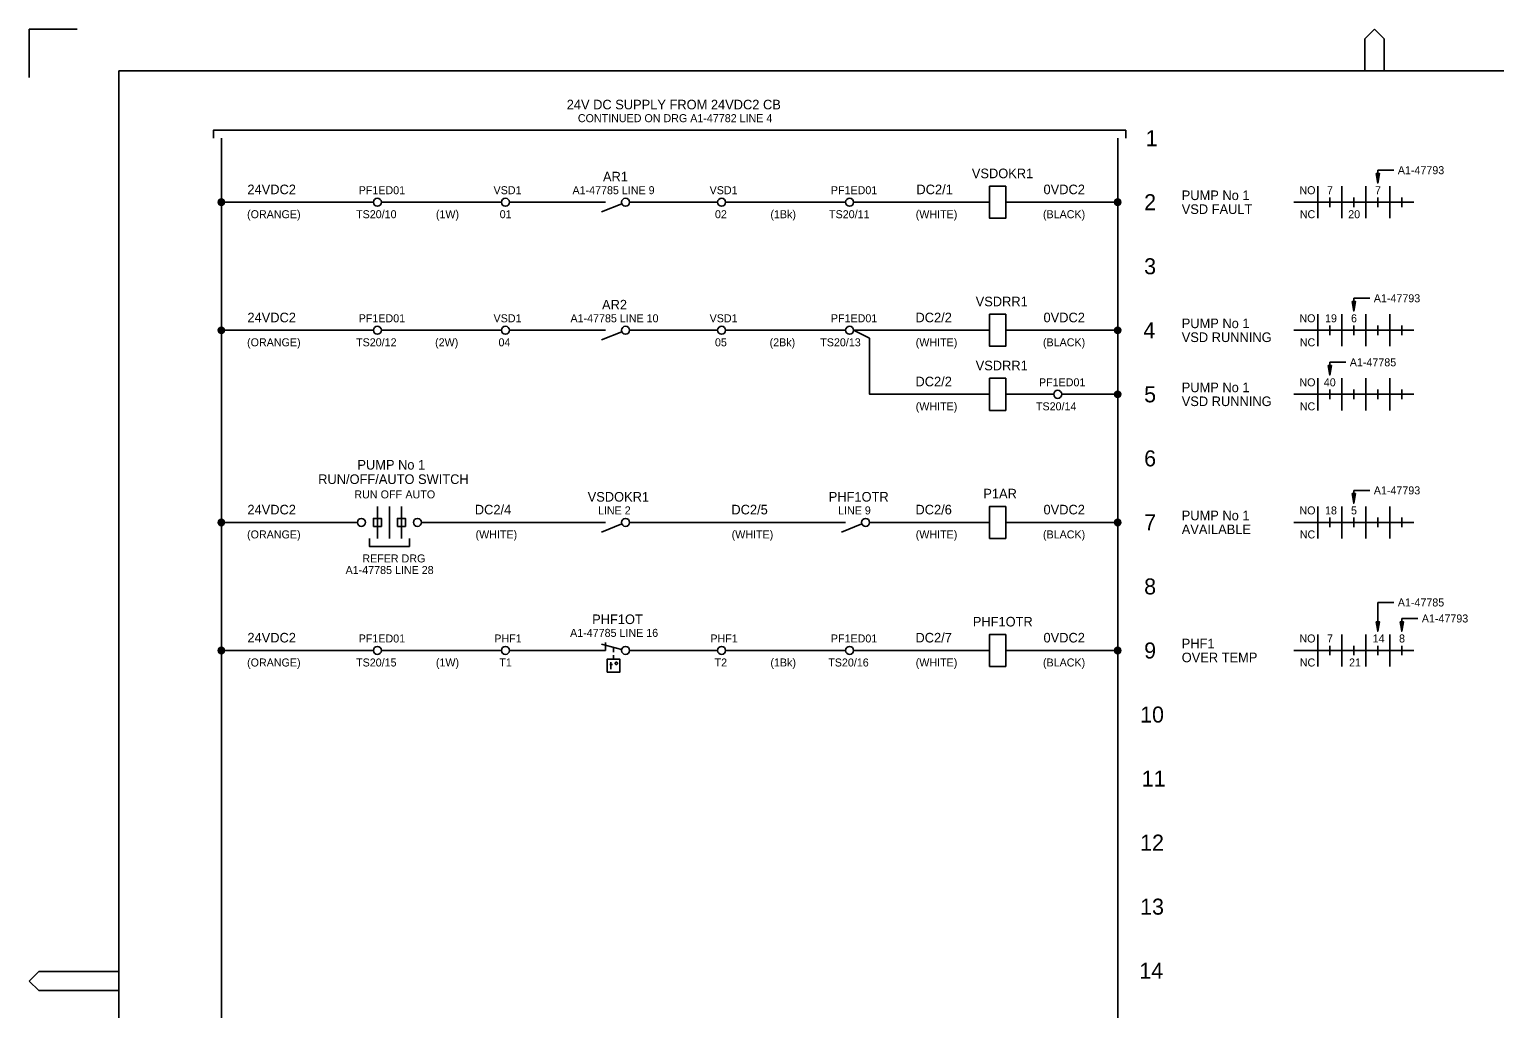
# Model space of a CAD drawing. Extents: x 0 to 841, y 0 to 594.
# Drawn here: x 0 to 457.8, y 288.1 to 594 of the extents above; entities that cross this region are included whole.
import ezdxf

# ---------------------------------------------------------------- set-up
doc = ezdxf.new("R2010")
doc.units = 0
for name, color, linetype in [('A1BORDER', 7, 'Continuous'), ('Level 1', 7, 'Continuous'), ('Level 10', 7, 'Continuous'), ('Level 5', 7, 'Continuous'), ('Level 6', 7, 'Continuous')]:
    doc.layers.add(name, color=color, linetype=linetype)

msp = doc.modelspace()

# ---------------------------------------------------------------- linework, layer by layer
at = {"layer": 'A1BORDER'}
for p, q in [((0, 594), (15, 594)), ((0, 579), (0, 594)), ((417.19, 591), (420.19, 594)), ((417.19, 581), (417.19, 591)), ((423.19, 591), (420.19, 594)), ((423.19, 581), (423.19, 591)), ((28, 581), (829, 581)), ((28, 581), (28, 15)), ((3, 299.76), (0, 296.76)), ((28, 299.76), (3, 299.76)), ((3, 293.76), (0, 296.76)), ((28, 293.76), (3, 293.76))]:
    msp.add_line(p, q, dxfattribs=at)
at = {"layer": 'Level 1'}
for p, q in [((60, 160), (60, 560)), ((340, 160), (340, 560)), ((402.5, 535), (402.5, 545)), ((410, 535), (410, 545)), ((417.5, 535), (417.5, 545)), ((425, 535), (425, 545)), ((406.25, 541.5), (406.25, 538.5)), ((413.75, 541.5), (413.75, 538.5)), ((421.25, 541.5), (421.25, 538.5)), ((428.75, 541.5), (428.75, 538.5)), ((60, 540), (107.5, 540)), ((147.5, 540), (110, 540)), ((177.5, 540), (150, 540)), ((180, 540), (177.5, 540)), ((177.5, 540), (177.5, 540)), ((215, 540), (187.5, 540)), ((187.5, 540), (187.5, 540)), ((255, 540), (217.5, 540)), ((305, 540), (340, 540)), ((395, 540), (432.5, 540)), ((60, 140), (60, 520)), ((340, 140), (340, 520)), ((402.5, 495), (402.5, 505)), ((410, 495), (410, 505)), ((417.5, 495), (417.5, 505)), ((425, 495), (425, 505)), ((60, 500), (107.5, 500)), ((147.5, 500), (110, 500)), ((177.5, 500), (150, 500)), ((180, 500), (177.5, 500)), ((177.5, 500), (177.5, 500)), ((215, 500), (187.5, 500)), ((187.5, 500), (187.5, 500)), ((255, 500), (217.5, 500)), ((305, 500), (340, 500)), ((395, 500), (432.5, 500)), ((406.25, 501.5), (406.25, 498.5)), ((413.75, 501.5), (413.75, 498.5)), ((421.25, 501.5), (421.25, 498.5)), ((428.75, 501.5), (428.75, 498.5)), ((402.5, 475), (402.5, 485)), ((406.25, 481.5), (406.25, 478.5)), ((410, 475), (410, 485)), ((413.75, 481.5), (413.75, 478.5)), ((417.5, 475), (417.5, 485)), ((421.25, 481.5), (421.25, 478.5)), ((425, 475), (425, 485)), ((428.75, 481.5), (428.75, 478.5)), ((305, 480), (320, 480)), ((322.5, 480), (340, 480)), ((395, 480), (432.5, 480)), ((108.75, 445), (108.75, 435)), ((112.5, 445), (112.5, 435)), ((116.25, 445), (116.25, 435)), ((402.5, 435), (402.5, 445)), ((410, 435), (410, 445)), ((417.5, 435), (417.5, 445)), ((425, 435), (425, 445)), ((102.5, 440), (60, 440)), ((177.5, 440), (122.5, 440)), ((180, 440), (177.5, 440)), ((177.5, 440), (177.5, 440)), ((252.5, 440), (187.5, 440)), ((187.5, 440), (187.5, 440)), ((255, 440), (252.5, 440)), ((252.5, 440), (252.5, 440)), ((262.5, 440), (262.5, 440)), ((305, 440), (340, 440)), ((395, 440), (432.5, 440)), ((406.25, 441.5), (406.25, 438.5)), ((413.75, 441.5), (413.75, 438.5)), ((421.25, 441.5), (421.25, 438.5)), ((428.75, 441.5), (428.75, 438.5)), ((402.5, 395), (402.5, 405)), ((410, 395), (410, 405)), ((417.5, 395), (417.5, 405)), ((425, 395), (425, 405)), ((60, 400), (107.5, 400)), ((147.5, 400), (110, 400)), ((177.5, 400), (150, 400)), ((180, 400), (177.5, 400)), ((177.5, 400), (177.5, 400)), ((182.5, 401), (182.5, 399.5)), ((182.5, 398.5), (182.5, 397.25)), ((215, 400), (187.5, 400)), ((187.5, 400), (187.5, 400)), ((255, 400), (217.5, 400)), ((305, 400), (340, 400)), ((395, 400), (432.5, 400)), ((406.25, 401.5), (406.25, 398.5)), ((413.75, 401.5), (413.75, 398.5)), ((421.25, 401.5), (421.25, 398.5)), ((428.75, 401.5), (428.75, 398.5))]:
    msp.add_line(p, q, dxfattribs=at)
for points in [[(57.5, 560), (57.5, 562.5), (342.5, 562.5), (342.5, 560)], [(257.5, 500), (262.5, 497.5), (262.5, 480), (300, 480)], [(106.25, 435), (106.25, 432.5), (118.75, 432.5), (118.75, 435)], [(181.38, 395.63), (182.13, 395.63)], [(181.63, 396.38), (181.63, 394.12)], [(183.36, 395.63), (183.18, 395.67), (183.05, 395.81), (182.99, 396.01), (183.05, 396.19), (183.18, 396.32), (183.36, 396.38), (183.56, 396.32), (183.7, 396.19), (183.74, 396.01), (183.7, 395.81), (183.56, 395.67), (183.36, 395.63)]]:
    msp.add_lwpolyline(points, dxfattribs=at)
for points in [[(107.5, 438.75), (110, 438.75), (110, 441.25), (107.5, 441.25)], [(115, 438.75), (117.5, 438.75), (117.5, 441.25), (115, 441.25)], [(180.5, 393.25), (184.5, 393.25), (184.5, 397.25), (180.5, 397.25)]]:
    msp.add_lwpolyline(points, close=True, dxfattribs=at)
at = {"layer": 'Level 10'}
for p, q in [((59.1, 540.44), (59.1, 539.56)), ((59.4, 540.8), (59.4, 539.2)), ((59.7, 540.95), (59.7, 539.05)), ((60, 541), (60, 539.01)), ((60.3, 540.95), (60.3, 539.05)), ((60.6, 540.8), (60.6, 539.2)), ((60.9, 540.44), (60.9, 539.56)), ((339.1, 540.44), (339.1, 539.56)), ((339.4, 540.8), (339.4, 539.2)), ((339.7, 540.95), (339.7, 539.05)), ((340, 541), (340, 539.01)), ((340.3, 540.95), (340.3, 539.05)), ((340.6, 540.8), (340.6, 539.2)), ((340.9, 540.44), (340.9, 539.56)), ((61, 540), (61, 540)), ((185.09, 539.54), (178.75, 537)), ((341, 540), (341, 540)), ((59.1, 500.44), (59.1, 499.56)), ((59.4, 500.8), (59.4, 499.2)), ((59.7, 500.95), (59.7, 499.05)), ((60, 501), (60, 499.01)), ((60.3, 500.95), (60.3, 499.05)), ((60.6, 500.8), (60.6, 499.2)), ((60.9, 500.44), (60.9, 499.56)), ((61, 500), (61, 500)), ((185.09, 499.54), (178.75, 497)), ((339.1, 500.44), (339.1, 499.56)), ((339.4, 500.8), (339.4, 499.2)), ((339.7, 500.95), (339.7, 499.05)), ((340, 501), (340, 499.01)), ((340.3, 500.95), (340.3, 499.05)), ((340.6, 500.8), (340.6, 499.2)), ((340.9, 500.44), (340.9, 499.56)), ((341, 500), (341, 500)), ((339.4, 480.8), (339.4, 479.2)), ((339.7, 480.95), (339.7, 479.05)), ((340, 481), (340, 479.01)), ((340.3, 480.95), (340.3, 479.05)), ((340.6, 480.8), (340.6, 479.2)), ((339.1, 480.44), (339.1, 479.56)), ((340.9, 480.44), (340.9, 479.56)), ((341, 480), (341, 480)), ((59.1, 440.44), (59.1, 439.56)), ((59.4, 440.8), (59.4, 439.2)), ((59.7, 440.95), (59.7, 439.05)), ((60, 441), (60, 439.01)), ((60.3, 440.95), (60.3, 439.05)), ((60.6, 440.8), (60.6, 439.2)), ((60.9, 440.44), (60.9, 439.56)), ((61, 440), (61, 440)), ((185.09, 439.54), (178.75, 437)), ((260.09, 439.54), (253.75, 437)), ((339.1, 440.44), (339.1, 439.56)), ((339.4, 440.8), (339.4, 439.2)), ((339.7, 440.95), (339.7, 439.05)), ((340, 441), (340, 439.01)), ((340.3, 440.95), (340.3, 439.05)), ((340.6, 440.8), (340.6, 439.2)), ((340.9, 440.44), (340.9, 439.56)), ((341, 440), (341, 440)), ((59.1, 400.44), (59.1, 399.56)), ((59.4, 400.8), (59.4, 399.2)), ((59.7, 400.95), (59.7, 399.05)), ((60, 401), (60, 399.01)), ((60.3, 400.95), (60.3, 399.05)), ((60.6, 400.8), (60.6, 399.2)), ((60.9, 400.44), (60.9, 399.56)), ((61, 400), (61, 400)), ((185.04, 400.32), (178.75, 402)), ((180, 402.5), (180, 400)), ((339.1, 400.44), (339.1, 399.56)), ((339.4, 400.8), (339.4, 399.2)), ((339.7, 400.95), (339.7, 399.05)), ((340, 401), (340, 399.01)), ((340.3, 400.95), (340.3, 399.05)), ((340.6, 400.8), (340.6, 399.2)), ((340.9, 400.44), (340.9, 399.56)), ((341, 400), (341, 400))]:
    msp.add_line(p, q, dxfattribs=at)
for points in [[(305, 545), (305, 535), (300, 535), (300, 545), (305, 545)], [(305, 505), (305, 495), (300, 495), (300, 505), (305, 505)], [(305, 485), (305, 475), (300, 475), (300, 485), (305, 485)], [(305, 445), (305, 435), (300, 435), (300, 445), (305, 445)], [(305, 405), (305, 395), (300, 395), (300, 405), (305, 405)]]:
    msp.add_lwpolyline(points, dxfattribs=at)
for centre, radius in [((60, 540), 1), ((186.25, 540), 1.25), ((340, 540), 1), ((60, 500), 1), ((186.25, 500), 1.25), ((340, 500), 1), ((340, 480), 1), ((60, 440), 1), ((186.25, 440), 1.25), ((261.25, 440), 1.25), ((340, 440), 1), ((60, 400), 1), ((186.25, 400), 1.25), ((340, 400), 1)]:
    msp.add_circle(centre, radius, dxfattribs=at)
at = {"layer": 'Level 5'}
for centre in [(108.75, 540), (148.75, 540), (216.25, 540), (256.25, 540), (108.75, 500), (148.75, 500), (216.25, 500), (256.25, 500), (321.25, 480), (103.75, 440), (121.25, 440), (108.75, 400), (148.75, 400), (216.25, 400), (256.25, 400)]:
    msp.add_circle(centre, 1.25, dxfattribs=at)
at = {"layer": 'Level 6'}
for p, q in [((421.25, 546.5), (421.25, 550)), ((421.25, 550), (426.25, 550)), ((257.5, 540), (300, 540)), ((413.75, 506.5), (413.75, 510)), ((413.75, 510), (418.75, 510)), ((257.5, 500), (300, 500)), ((406.25, 486.5), (406.25, 490)), ((406.25, 490), (411.25, 490)), ((413.75, 446.5), (413.75, 450)), ((413.75, 450), (418.75, 450)), ((262.5, 440), (300, 440)), ((421.25, 406.5), (421.25, 415)), ((421.25, 415), (426.25, 415)), ((428.75, 406.5), (428.75, 410)), ((428.75, 410), (433.75, 410)), ((257.5, 400), (300, 400))]:
    msp.add_line(p, q, dxfattribs=at)
for points in [[(420.75, 549), (421.25, 546), (421.75, 549)], [(413.25, 509), (413.75, 506), (414.25, 509)], [(405.75, 489), (406.25, 486), (406.75, 489)], [(413.25, 449), (413.75, 446), (414.25, 449)], [(420.75, 409), (421.25, 406), (421.75, 409)], [(428.25, 409), (428.75, 406), (429.25, 409)]]:
    msp.add_lwpolyline(points, close=True, dxfattribs=at)

# ---------------------------------------------------------------- texts
at = {"layer": 'Level 1'}
for s, height, p in [('24V DC SUPPLY FROM 24VDC2 CB', 3, (167.88, 569)), ('CONTINUED ON DRG A1-47782 LINE 4', 2.5, (171.36, 565)), ('1', 5, (348.75, 557.5)), ('PF1ED01', 2.5, (102.9, 542.5)), ('VSD1', 2.5, (145.02, 542.5)), ('VSD1', 2.5, (212.52, 542.5)), ('PF1ED01', 2.5, (250.4, 542.5)), ('NO', 2.5, (396.76, 542.5)), ('7', 2.5, (405.38, 542.5)), ('7', 2.5, (420.38, 542.5)), ('2', 5, (348.26, 537.5)), ('NC', 2.5, (396.88, 535)), ('20', 2.5, (412.01, 535)), ('3', 5, (348.26, 517.5)), ('PF1ED01', 2.5, (102.9, 502.5)), ('VSD1', 2.5, (145.02, 502.5)), ('VSD1', 2.5, (212.52, 502.5)), ('PF1ED01', 2.5, (250.4, 502.5)), ('NO', 2.5, (396.76, 502.5)), ('19', 2.5, (404.76, 502.5)), ('6', 2.5, (412.88, 502.5)), ('4', 5, (348.01, 497.5)), ('NC', 2.5, (396.88, 495)), ('PF1ED01', 2.5, (315.4, 482.5)), ('5', 5, (348.26, 477.5)), ('NO', 2.5, (396.76, 482.5)), ('40', 2.5, (404.38, 482.5)), ('NC', 2.5, (396.88, 475)), ('6', 5, (348.26, 457.5)), ('PUMP No 1', 3, (102.49, 456.5)), ('RUN/OFF/AUTO SWITCH', 3, (90.24, 452)), ('RUN', 2.5, (101.52, 447.5)), ('OFF', 2.5, (109.76, 447.5)), ('AUTO', 2.5, (117.5, 447.5)), ('NO', 2.5, (396.76, 442.5)), ('18', 2.5, (404.76, 442.5)), ('5', 2.5, (412.88, 442.5)), ('7', 5, (348.26, 437.5)), ('NC', 2.5, (396.88, 435)), ('A1-47785 LINE 28', 2.5, (98.8, 423.88)), ('REFER DRG', 2.5, (104.03, 427.5)), ('8', 5, (348.26, 417.5)), ('PF1ED01', 2.5, (102.9, 402.5)), ('PHF1', 2.5, (145.26, 402.5)), ('PHF1', 2.5, (212.76, 402.5)), ('PF1ED01', 2.5, (250.4, 402.5)), ('NO', 2.5, (396.76, 402.5)), ('7', 2.5, (405.38, 402.5)), ('14', 2.5, (419.63, 402.5)), ('8', 2.5, (427.88, 402.5)), ('9', 5, (348.26, 397.5)), ('NC', 2.5, (396.88, 395)), ('21', 2.5, (412.26, 395)), ('10', 5, (347.01, 377.5)), ('11', 5, (347.51, 357.5)), ('12', 5, (347.01, 337.5)), ('13', 5, (347.01, 317.5)), ('14', 5, (346.76, 297.5))]:
    msp.add_text(s, height=height, dxfattribs=at).set_placement(p)
at = {"layer": 'Level 5'}
for s, height, p in [('AR1', 3, (179.21, 546.5)), ('VSDOKR1', 3, (294.43, 547.5)), ('A1-47793', 2.5, (427.5, 548.75)), ('24VDC2', 3, (68.13, 542.5)), ('A1-47785 LINE 9', 2.5, (169.68, 542.5)), ('DC2/1', 3, (277.12, 542.5)), ('0VDC2', 3, (316.82, 542.5)), ('PUMP No 1', 3, (360, 540.67)), ('(ORANGE)', 2.5, (68.03, 535)), ('TS20/10', 2.5, (102.08, 535)), ('(1W)', 2.5, (127.01, 535)), ('01', 2.5, (146.94, 535)), ('02', 2.5, (214.19, 535)), ('(1Bk)', 2.5, (231.51, 535)), ('TS20/11', 2.5, (249.83, 535)), ('(WHITE)', 2.5, (276.9, 535)), ('(BLACK)', 2.5, (316.65, 535)), ('VSD FAULT', 3, (360, 536.33)), ('AR2', 3, (178.91, 506.5)), ('VSDRR1', 3, (295.63, 507.5)), ('A1-47793', 2.5, (420, 508.75)), ('24VDC2', 3, (68.13, 502.5)), ('A1-47785 LINE 10', 2.5, (169.05, 502.5)), ('DC2/2', 3, (276.82, 502.5)), ('0VDC2', 3, (316.82, 502.5)), ('PUMP No 1', 3, (360, 500.67)), ('VSD RUNNING', 3, (360, 496.33)), ('(ORANGE)', 2.5, (68.03, 495)), ('TS20/12', 2.5, (102.08, 495)), ('(2W)', 2.5, (126.76, 495)), ('04', 2.5, (146.57, 495)), ('05', 2.5, (214.19, 495)), ('(2Bk)', 2.5, (231.26, 495)), ('TS20/13', 2.5, (247.08, 495)), ('(WHITE)', 2.5, (276.9, 495)), ('(BLACK)', 2.5, (316.65, 495)), ('VSDRR1', 3, (295.63, 487.5)), ('A1-47785', 2.5, (412.5, 488.75)), ('DC2/2', 3, (276.82, 482.5)), ('PUMP No 1', 3, (360, 480.67)), ('(WHITE)', 2.5, (276.9, 475)), ('TS20/14', 2.5, (314.46, 475)), ('VSD RUNNING', 3, (360, 476.33)), ('VSDOKR1', 3, (174.43, 446.5)), ('PHF1OTR', 3, (249.73, 446.5)), ('P1AR', 3, (298.02, 447.5)), ('A1-47793', 2.5, (420, 448.75)), ('24VDC2', 3, (68.13, 442.5)), ('DC2/4', 3, (139.17, 442.5)), ('LINE 2', 2.5, (177.64, 442.5)), ('DC2/5', 3, (219.32, 442.5)), ('LINE 9', 2.5, (252.64, 442.5)), ('DC2/6', 3, (276.82, 442.5)), ('0VDC2', 3, (316.82, 442.5)), ('PUMP No 1', 3, (360, 440.67)), ('(ORANGE)', 2.5, (68.03, 435)), ('(WHITE)', 2.5, (139.4, 435)), ('(WHITE)', 2.5, (219.4, 435)), ('(WHITE)', 2.5, (276.9, 435)), ('(BLACK)', 2.5, (316.65, 435)), ('AVAILABLE', 3, (360, 436.33)), ('A1-47785', 2.5, (427.5, 413.75)), ('PHF1OT', 3, (175.82, 408.25)), ('PHF1OTR', 3, (294.73, 407.5)), ('A1-47793', 2.5, (435, 408.75)), ('24VDC2', 3, (68.13, 402.5)), ('A1-47785 LINE 16', 2.5, (168.94, 404.25)), ('DC2/7', 3, (276.82, 402.5)), ('0VDC2', 3, (316.82, 402.5)), ('PHF1', 3, (360, 400.67)), ('OVER TEMP', 3, (360, 396.33)), ('(ORANGE)', 2.5, (68.03, 395)), ('TS20/15', 2.5, (102.08, 395)), ('(1W)', 2.5, (127.01, 395)), ('T1', 2.5, (146.81, 395)), ('T2', 2.5, (214.07, 395)), ('(1Bk)', 2.5, (231.51, 395)), ('TS20/16', 2.5, (249.58, 395)), ('(WHITE)', 2.5, (276.9, 395)), ('(BLACK)', 2.5, (316.65, 395))]:
    msp.add_text(s, height=height, dxfattribs=at).set_placement(p)

doc.saveas('drawing.dxf')
